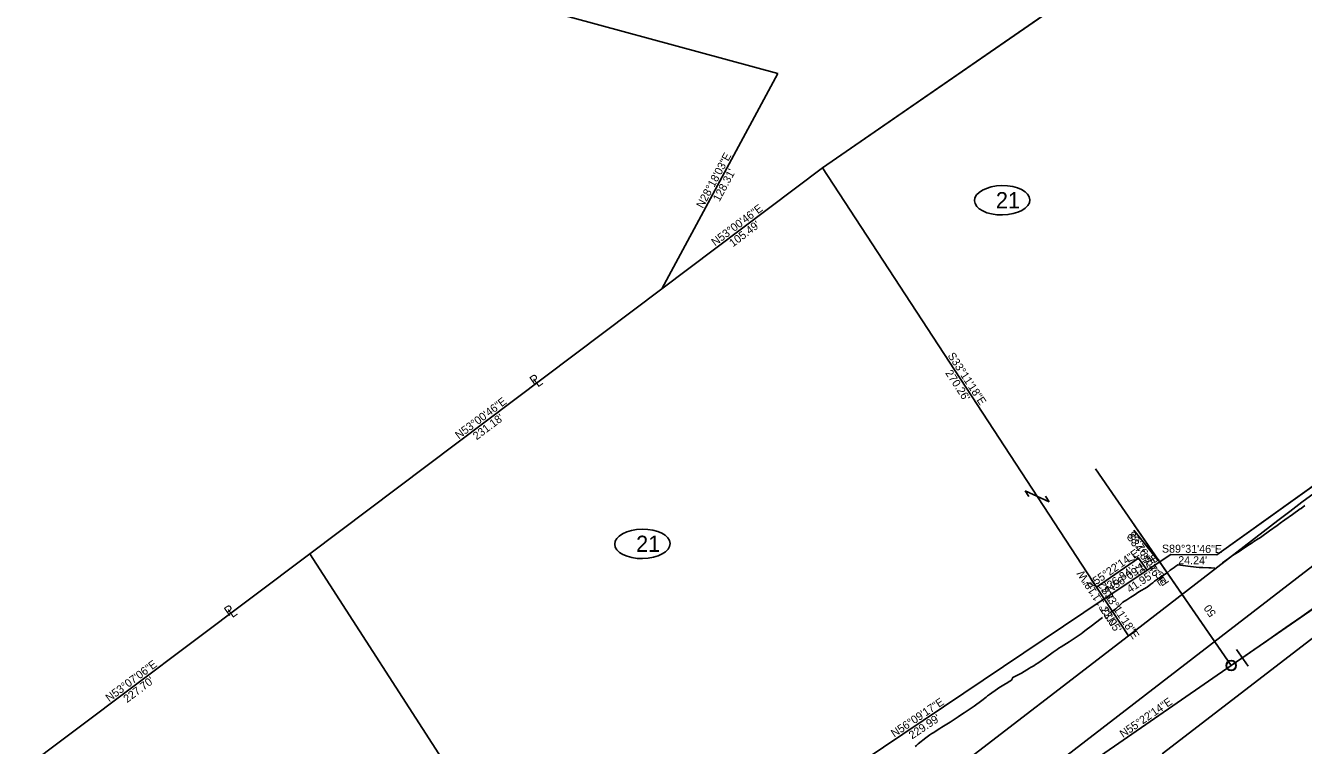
# Model space of a CAD drawing. Extents: x 1145508 to 2262867, y -3126236 to 2021677.
# Drawn here: x 1147661 to 1148331, y 2017985 to 2018362 of the extents above; entities that cross this region are included whole.
import ezdxf

# ---------------------------------------------------------------- set-up
doc = ezdxf.new("R2010")
doc.units = 0
for name, color, linetype in [('Default', 7, 'Continuous'), ('DSN_RDWY_Alignment', 7, 'Continuous'), ('DSN_RDWY_Alignment Annotation', 7, 'Continuous'), ('DSN_RDWY_Const Limits', 7, 'Continuous'), ('DSN_ROW_Annotation', 7, 'Continuous'), ('DSN_ROW_Esmnt', 7, 'Continuous'), ('DSN_ROW_Line', 7, 'Continuous'), ('DSN_ROW_Line-Annotation', 7, 'Continuous'), ('DSN_ROW_Prop-Line', 7, 'Continuous'), ('DSN_ROW_Prop-Line-Annotation', 7, 'Continuous'), ('E_Const Align', 7, 'Continuous'), ('EX_ROW', 7, 'Continuous'), ('EX_SIGN', 7, 'Continuous'), ('EX_WATER_UTILITIES_ANNOT', 7, 'Continuous')]:
    doc.layers.add(name, color=color, linetype=linetype)

msp = doc.modelspace()

# ---------------------------------------------------------------- linework, layer by layer
at = {"layer": 'Default'}
msp.add_line((1148336.03, 2018078.83), (1147725.18, 2017608.51), dxfattribs=at)
at = {"layer": 'DSN_RDWY_Alignment'}
msp.add_line((1148293.22, 2018026.54), (1148491.47, 2018163.46), dxfattribs=at)
msp.add_lwpolyline([(1148293.22, 2018026.54), (1148221.99, 2018129.68)], dxfattribs=at)
msp.add_circle((1148293.22, 2018026.54), 2.5, dxfattribs=at)
at = {"layer": 'DSN_RDWY_Alignment Annotation'}
for p, q in [((1148291.7, 2018028.74), (1148242.07, 2018100.6)), ((1148242.07, 2018100.6), (1148242.07, 2018100.6)), ((1148296.03, 2018034.98), (1148302.08, 2018026.25)), ((1148293.22, 2018026.54), (1148293.22, 2018026.54))]:
    msp.add_line(p, q, dxfattribs=at)
msp.add_circle((1148293.22, 2018026.54), 2.67, dxfattribs=at)
at = {"layer": 'DSN_RDWY_Const Limits'}
for points in [[(1148288.65, 2018080.48), (1148291.86, 2018082.74), (1148292.71, 2018083.33), (1148294.86, 2018084.79), (1148295.65, 2018085.31), (1148296.83, 2018086.09), (1148300.97, 2018088.82), (1148304.69, 2018091.27), (1148305.12, 2018091.55), (1148307.42, 2018093.06), (1148308.01, 2018093.44), (1148309.27, 2018094.27), (1148313.32, 2018097.14), (1148317.34, 2018100.03), (1148317.36, 2018100.04), (1148319.64, 2018101.67), (1148320.16, 2018102.05), (1148321.38, 2018102.92), (1148325.41, 2018105.8), (1148329.45, 2018108.68), (1148329.9, 2018109), (1148331.9, 2018110.42)], [(1148230.13, 2018054.59), (1148232.65, 2018056.37), (1148236.43, 2018059.71), (1148238.48, 2018061.06), (1148239.51, 2018061.72), (1148240.62, 2018062.43), (1148242.3, 2018063.52), (1148244.84, 2018065.12), (1148249.13, 2018067.71), (1148251.1, 2018069.15), (1148252.04, 2018069.94), (1148253.07, 2018070.81), (1148257.2, 2018073.63), (1148259.59, 2018075.23), (1148261.26, 2018076.5), (1148263.27, 2018077.99), (1148264.1, 2018078.59), (1148265.25, 2018079.44), (1148271.96, 2018078.44), (1148276.36, 2018078.05), (1148278.34, 2018077.94), (1148281.57, 2018077.77), (1148282.79, 2018077.71), (1148284.6, 2018077.62)], [(1148127.34, 2017984.11), (1148128.04, 2017984.66), (1148129.03, 2017985.44), (1148133, 2017988.57), (1148135.15, 2017990.11), (1148136.23, 2017990.85), (1148137.14, 2017991.47), (1148139.53, 2017993.06), (1148140.31, 2017993.52), (1148141.41, 2017994.17), (1148145.78, 2017996.76), (1148149.5, 2017999.2), (1148149.99, 2017999.54), (1148152.31, 2018001.12), (1148153.1, 2018001.66), (1148154.17, 2018002.38), (1148158.36, 2018005.2), (1148162.37, 2018008.12), (1148162.45, 2018008.18), (1148164.62, 2018009.86), (1148165.35, 2018010.56), (1148166.36, 2018011.39), (1148170.54, 2018014.23), (1148171.31, 2018014.76), (1148171.38, 2018014.8), (1148174.8, 2018016.96), (1148175.15, 2018017.17), (1148177.02, 2018018.29), (1148178.03, 2018018.92), (1148178.58, 2018020.29), (1148183.15, 2018022.47), (1148187.41, 2018025.09), (1148188.01, 2018025.46), (1148189.6, 2018026.44), (1148190.61, 2018027.06), (1148191.69, 2018027.7), (1148195.81, 2018030.54), (1148199.82, 2018033.53), (1148201.96, 2018034.99), (1148202.86, 2018035.6), (1148203.95, 2018036.34), (1148208.16, 2018039.04), (1148212.38, 2018041.74), (1148214.45, 2018043.25), (1148215.33, 2018043.9), (1148216.42, 2018044.69), (1148220.39, 2018047.74), (1148224.39, 2018050.74), (1148225.78, 2018051.65)]]:
    msp.add_lwpolyline(points, dxfattribs=at)
at = {"layer": 'DSN_ROW_Esmnt'}
for p, q in [((1148222.6, 2018067.7), (1148244.68, 2018082.95)), ((1148244.68, 2018082.95), (1148249.11, 2018076.54)), ((1148226.66, 2018061.49), (1148222.6, 2018067.7))]:
    msp.add_line(p, q, dxfattribs=at)
at = {"layer": 'DSN_ROW_Line'}
for p, q in [((1148285.74, 2018084.65), (1148479.1, 2018223.18)), ((1148226.66, 2018061.49), (1148261.5, 2018084.85)), ((1148261.5, 2018084.85), (1148285.74, 2018084.65)), ((1148035.64, 2017933.4), (1148226.66, 2018061.49))]:
    msp.add_line(p, q, dxfattribs=at)
at = {"layer": 'DSN_ROW_Line-Annotation'}
for centre in [(1148173.07, 2018270.63), (1147984.29, 2018090.37)]:
    msp.add_ellipse(centre, major_axis=(14.54, 0.23), ratio=0.529773, dxfattribs=at)
at = {"layer": 'DSN_ROW_Prop-Line'}
for p, q in [((1148078.72, 2018287.66), (1148375.95, 2018492.82)), ((1148055.29, 2018337.16), (1147650.48, 2018447.32)), ((1147994.46, 2018224.19), (1148055.29, 2018337.16)), ((1147994.46, 2018224.19), (1148078.72, 2018287.66)), ((1148078.72, 2018287.66), (1148226.66, 2018061.49)), ((1147809.8, 2018085.11), (1147994.46, 2018224.19)), ((1147627.67, 2017948.45), (1147809.8, 2018085.11)), ((1147809.8, 2018085.11), (1147970.9, 2017835.56)), ((1148226.66, 2018061.49), (1148239.28, 2018042.2))]:
    msp.add_line(p, q, dxfattribs=at)
at = {"layer": 'DSN_ROW_Prop-Line-Annotation'}
for p, q in [((1148187, 2018115.29), (1148185.05, 2018118.26)), ((1148185.05, 2018118.26), (1148197.73, 2018112.4)), ((1148197.73, 2018112.4), (1148195.78, 2018115.36))]:
    msp.add_line(p, q, dxfattribs=at)
at = {"layer": 'E_Const Align'}
msp.add_line((1148208.89, 2017968.31), (1148293.22, 2018026.54), dxfattribs=at)
msp.add_arc((1145037.29, 2022741.09), 5729.58, 304.62946, 309.44534, dxfattribs=at)
msp.add_arc((1145037.29, 2022741.09), 5729.58, 304.62946, 309.44534, dxfattribs=at)
at = {"layer": 'EX_ROW'}
for p, q in [((1148239.28, 2018042.2), (1148317.73, 2018102.6)), ((1148354.33, 2018055.06), (1148257.09, 2017980.19)), ((1147970.9, 2017835.56), (1148239.28, 2018042.2))]:
    msp.add_line(p, q, dxfattribs=at)
msp.add_arc((1149334.71, 2016781.72), 1667.02, 118.87096, 127.59365, dxfattribs=at)
at = {"layer": 'EX_SIGN'}
msp.add_line((1148242.13, 2018097.63), (1148254.72, 2018081.86), dxfattribs=at)
at = {"layer": 'EX_WATER_UTILITIES_ANNOT'}
msp.add_lwpolyline([(1148078.72, 2018287.66), (1148226.66, 2018061.49), (1148261.5, 2018084.85), (1148285.74, 2018084.65), (1148479.1, 2018223.18), (1148517.78, 2018261.19), (1148375.95, 2018492.82)], close=True, dxfattribs=at)

# ---------------------------------------------------------------- texts
at = {"layer": 'DSN_RDWY_Alignment Annotation'}
for s, rotation, p in [('49+92.88', 124.62946, (1148255.48, 2018078.02)), ('PC', 124.62946, (1148260.88, 2018070.2)), ('50', 124.70063, (1148285.53, 2018053.84)), ('N55°22\'14"E', 34.62946, (1148236.51, 2017988.47))]:
    msp.add_text(s, height=4.2, rotation=rotation, dxfattribs=at).set_placement(p)
at = {"layer": 'DSN_ROW_Annotation'}
for s, rotation, p in [('N28°18\'03"E', 61.69918, (1148016, 2018266.09)), ("128.31'", 61.69918, (1148024.69, 2018269.58)), ('N53°00\'46"E', 36.98717, (1148022.43, 2018246.38)), ("105.49'", 36.98717, (1148031.79, 2018245.92)), ('S33°11\'18"E', 303.18839, (1148144.27, 2018189.1)), ("270.26'", 303.18839, (1148143.03, 2018180.03)), ('N53°00\'46"E', 36.98717, (1147887.97, 2018145.11)), ("231.18'", 36.98717, (1147897.32, 2018144.64)), ('S34°37\'46"E', 304.62946, (1148238.11, 2018094.05)), ('N55°22\'14"E', 34.62946, (1148219.09, 2018066.38)), ('S89°31\'46"E', 359.52953, (1148256.87, 2018085.79)), ('N56°09\'17"E', 33.84517, (1148229.41, 2018064.42)), ("7.79'", 304.62946, (1148239.03, 2018082.15)), ("24.24'", 359.52953, (1148265.43, 2018079.72)), ('N33°11\'18"W', 123.18839, (1148233.76, 2018048.98)), ("26.84'", 34.62946, (1148229.83, 2018066.5)), ("41.95'", 33.84517, (1148240.15, 2018064.39)), ("7.42'", 123.18839, (1148232.42, 2018061.99)), ('S33°11\'18"E', 303.18839, (1148224.55, 2018066.37)), ("23.05'", 303.18839, (1148224.24, 2018055.87)), ('N53°07\'06"E', 36.88153, (1147704.55, 2018007.26)), ("227.70'", 36.88153, (1147713.91, 2018006.78)), ('N56°09\'17"E', 33.84517, (1148116.48, 2017988.69)), ("229.99'", 33.84517, (1148125.8, 2017987.72))]:
    msp.add_text(s, height=4.2, rotation=rotation, dxfattribs=at).set_placement(p)
at = {"layer": 'DSN_ROW_Esmnt'}
msp.add_text('b', height=2, dxfattribs=at).set_placement((1148243.68, 2018081.95))
at = {"layer": 'DSN_ROW_Line-Annotation'}
for p in [(1148169.78, 2018266.42), (1147981, 2018086.16)]:
    msp.add_text('21', height=8.5, dxfattribs=at).set_placement(p)
at = {"layer": 'DSN_ROW_Prop-Line-Annotation'}
for s, p in [('P', (1147927.39, 2018173.21)), ('L', (1147929.45, 2018172.33)), ('P', (1147767.1, 2018052.21)), ('L', (1147769.16, 2018051.33))]:
    msp.add_text(s, height=5, rotation=35.45359, dxfattribs=at).set_placement(p)

doc.saveas('drawing.dxf')
